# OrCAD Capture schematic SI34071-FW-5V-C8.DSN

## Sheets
1 1.ETH_TR: size B; title: Si34071-FW-5V-C8-Interface; rev: 3.1; note: SI34071-FW-5V-C8
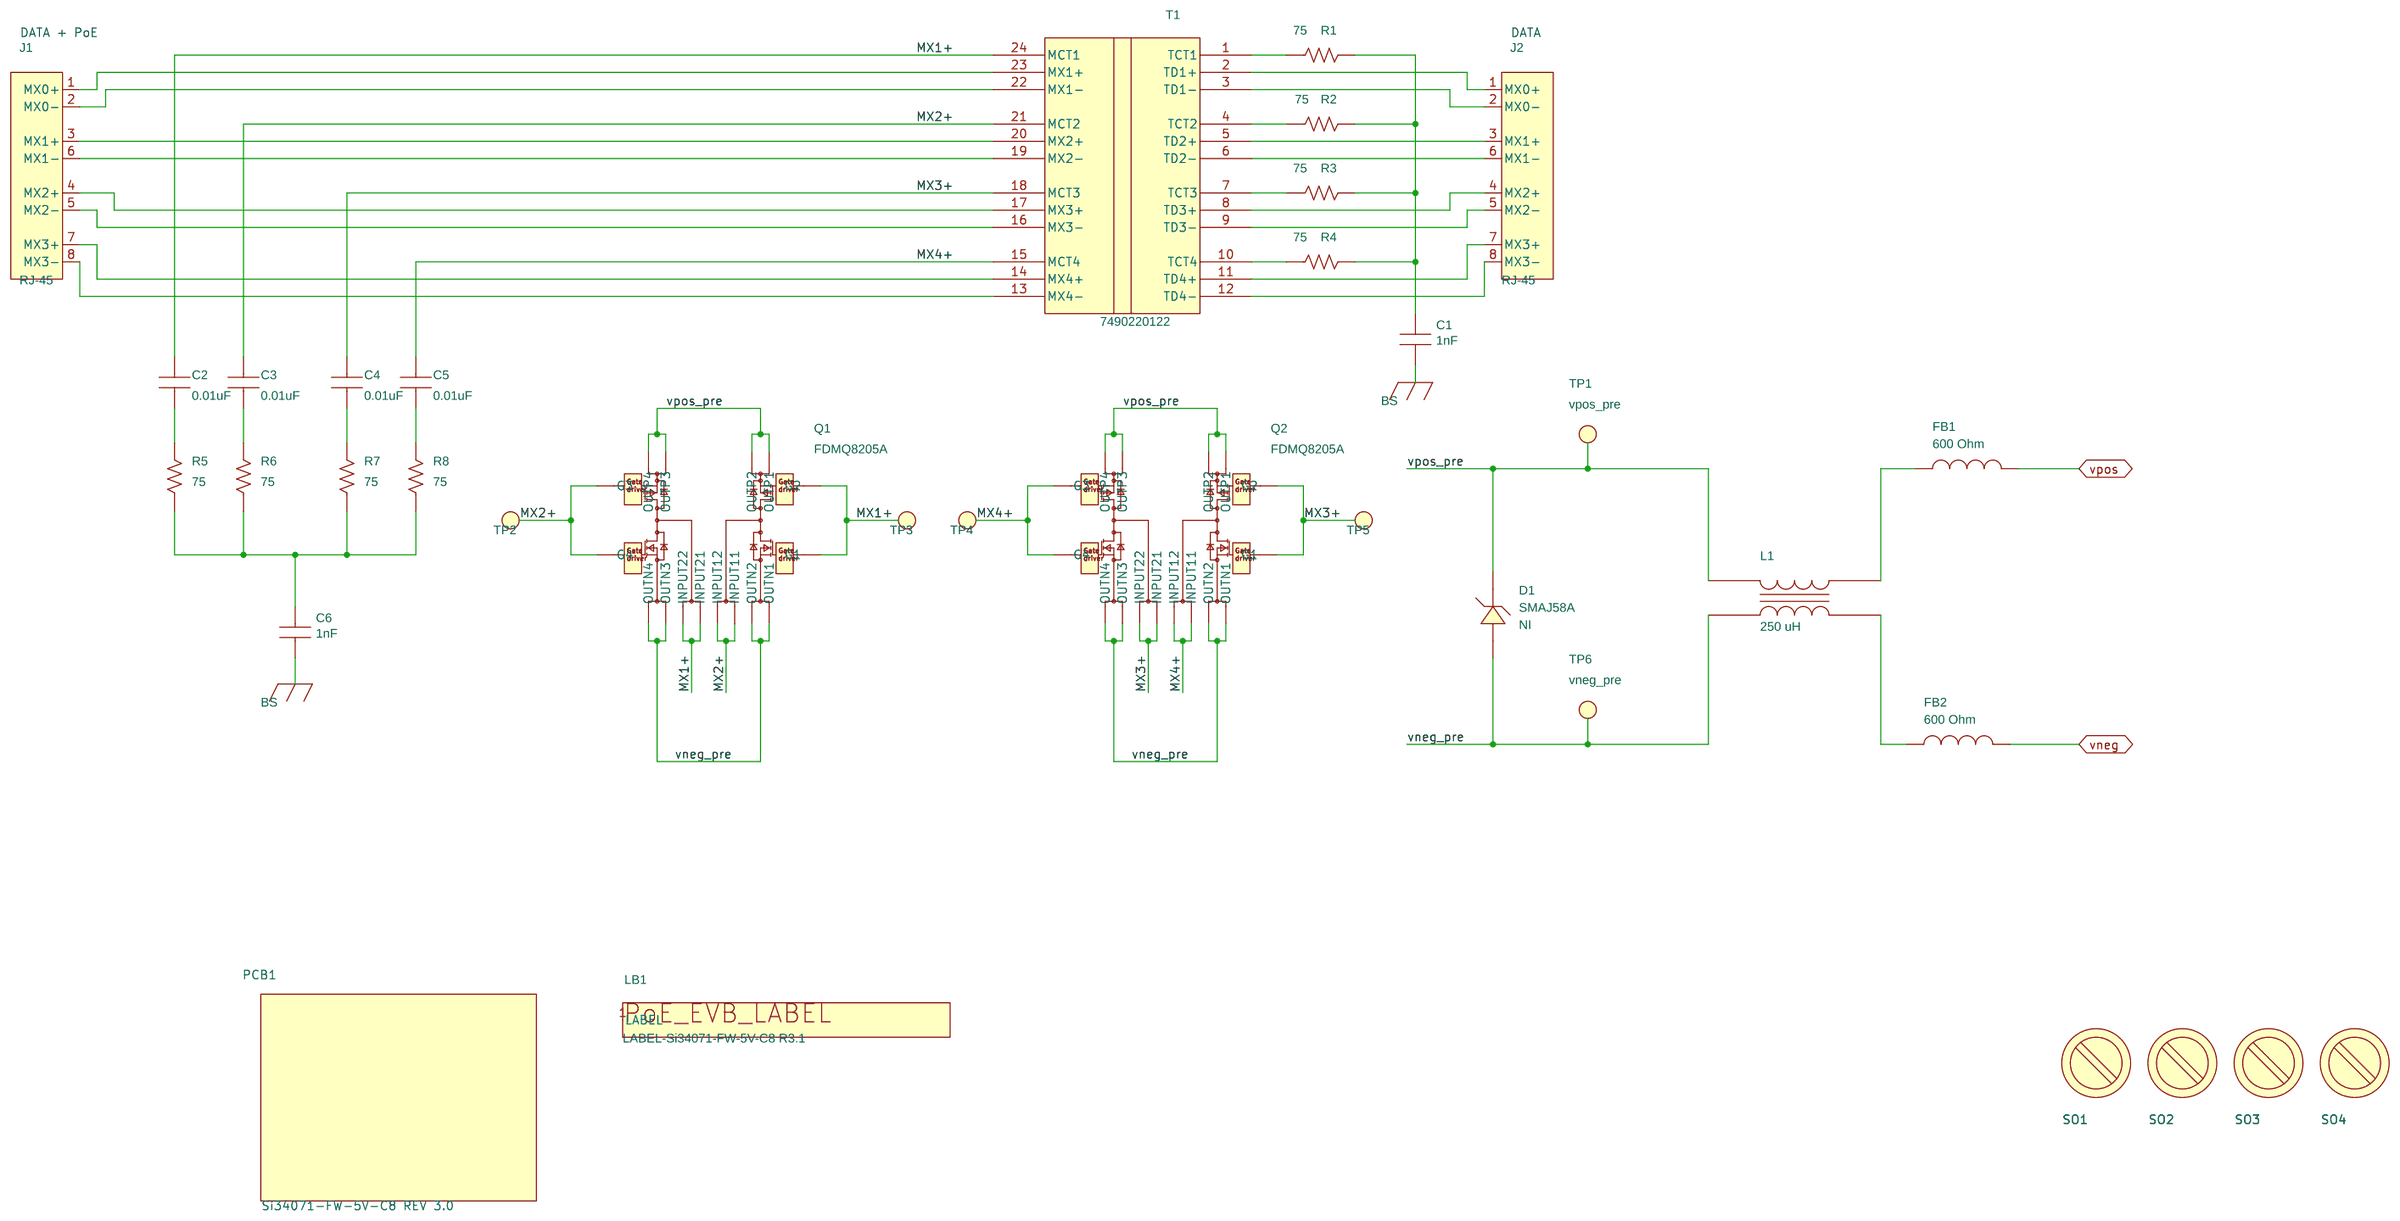
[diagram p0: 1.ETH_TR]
2 2.CLS_BOM: size B; title: Si34071-FW-5V-C8-Classification-BOM + MCU tx/rx
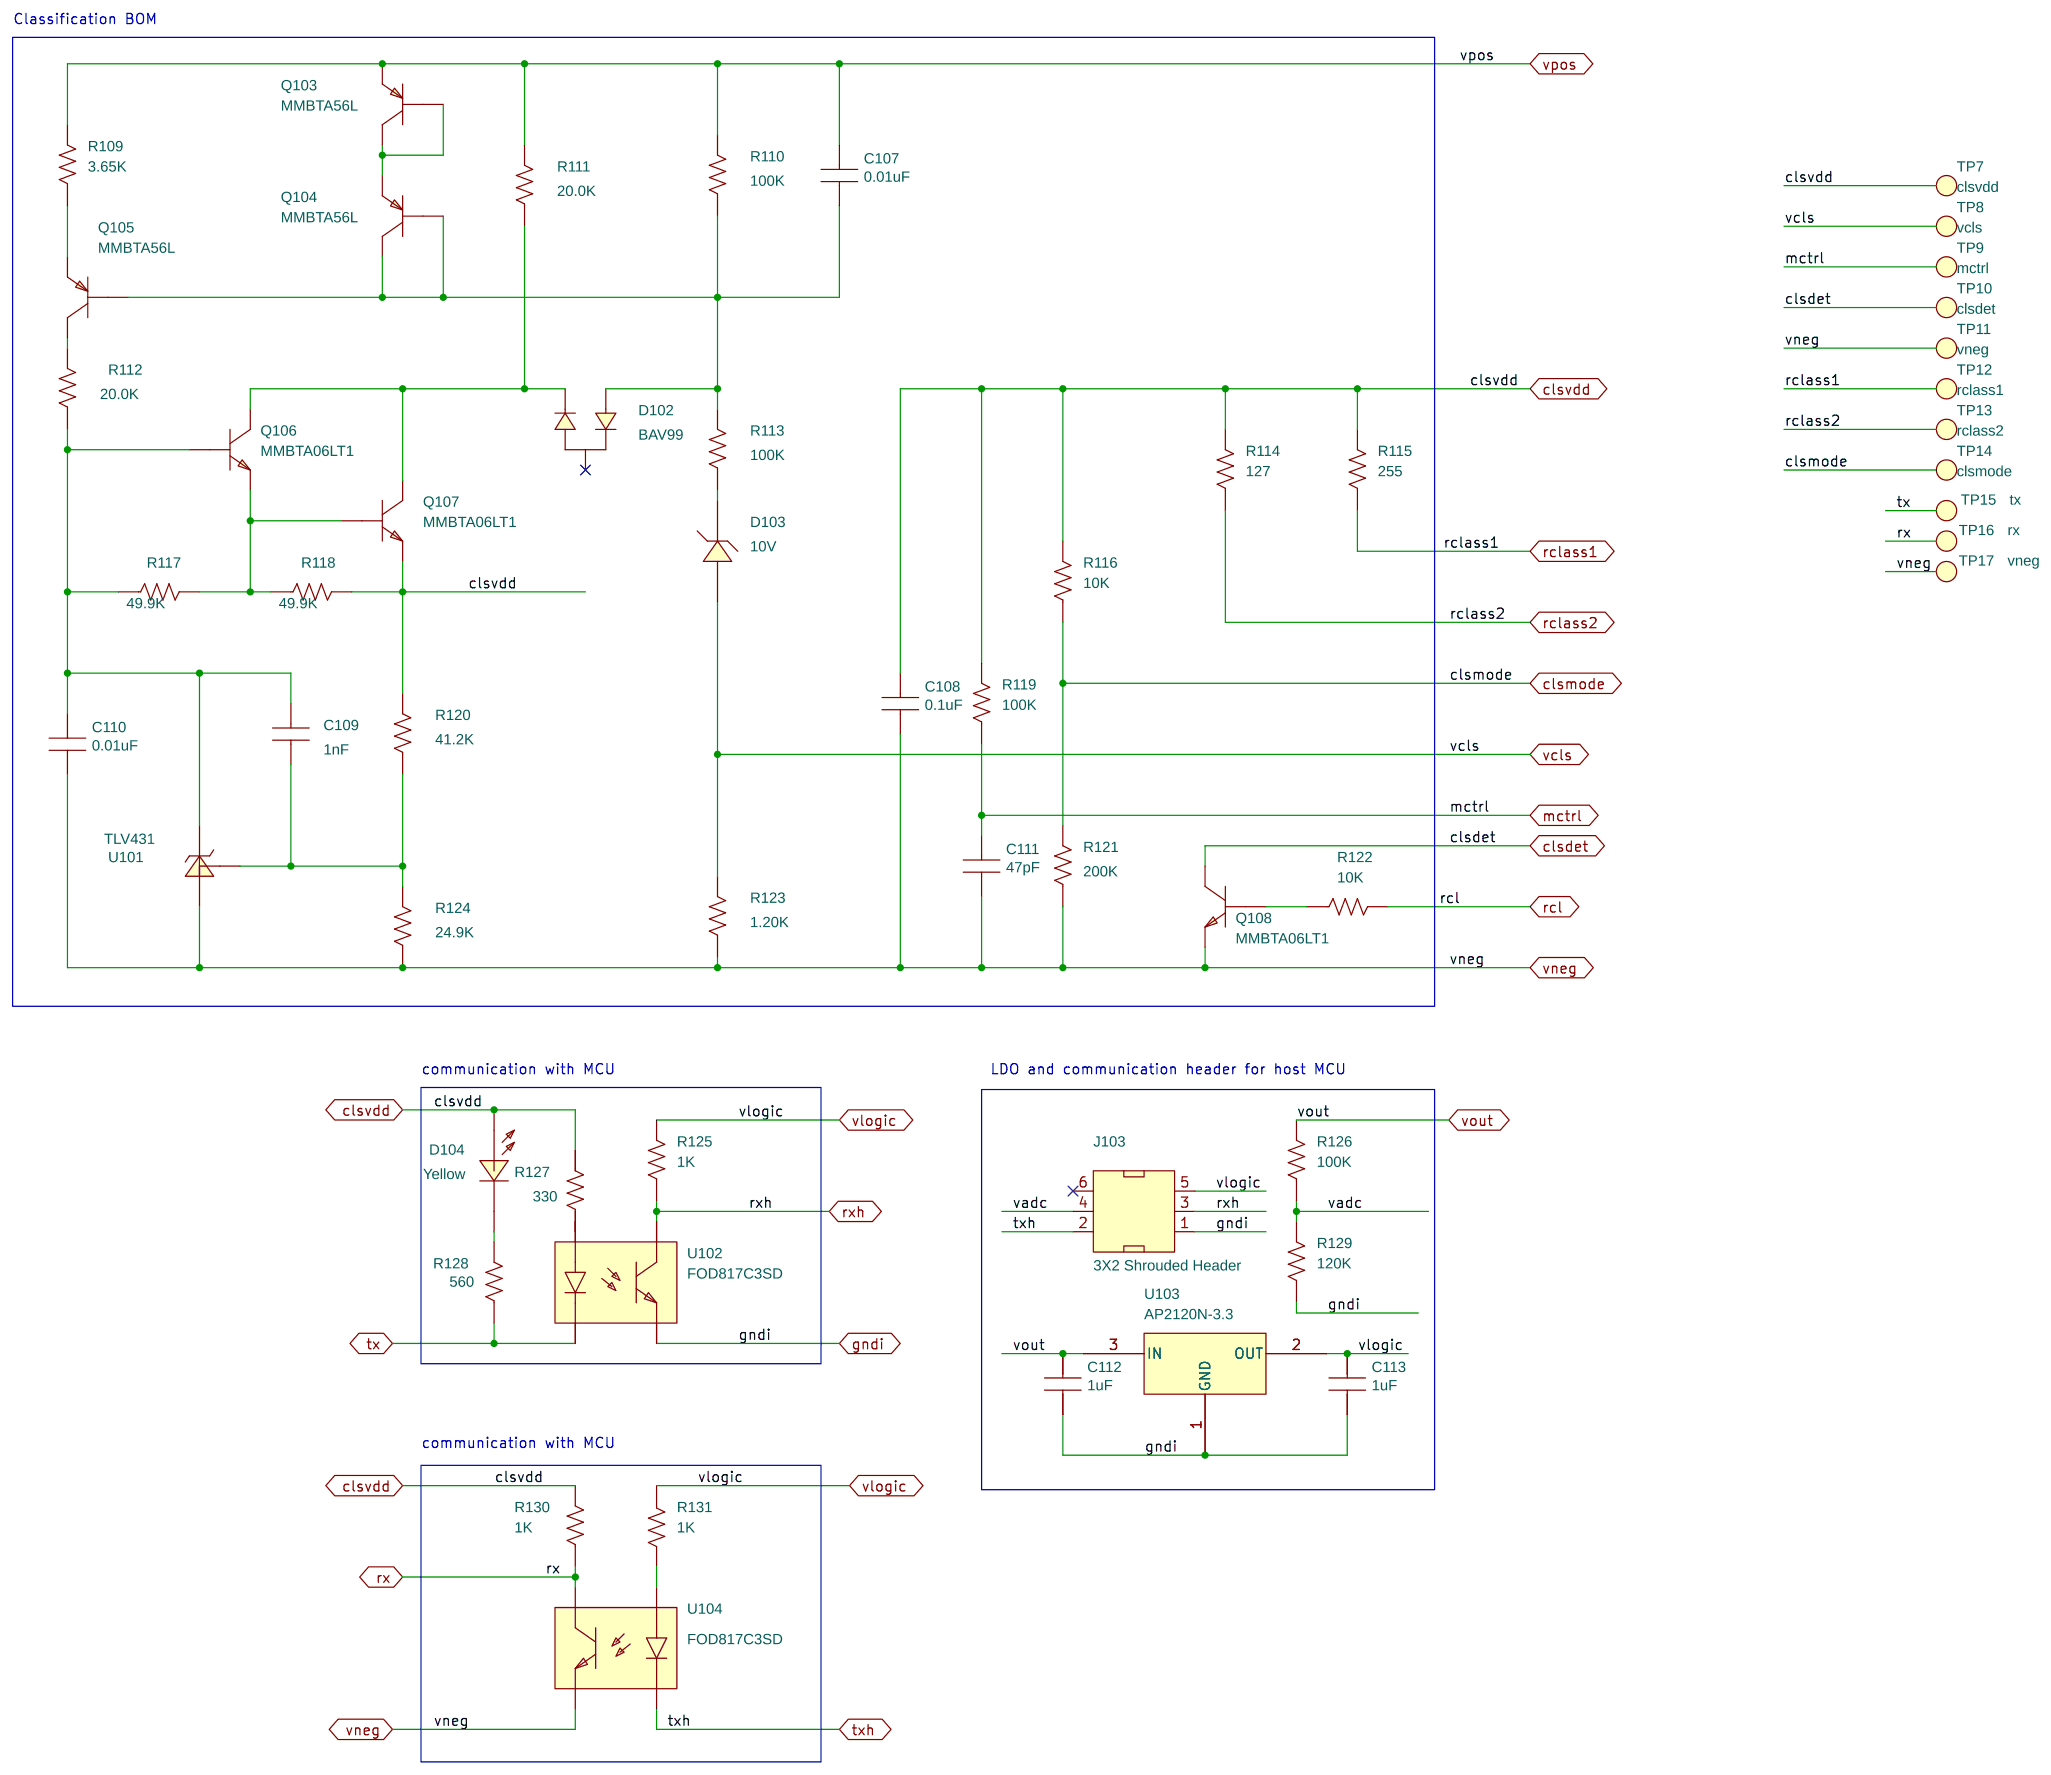
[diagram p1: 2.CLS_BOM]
3 3.DCDC: size B; title: Si34071-FW-5V-C8-Converter
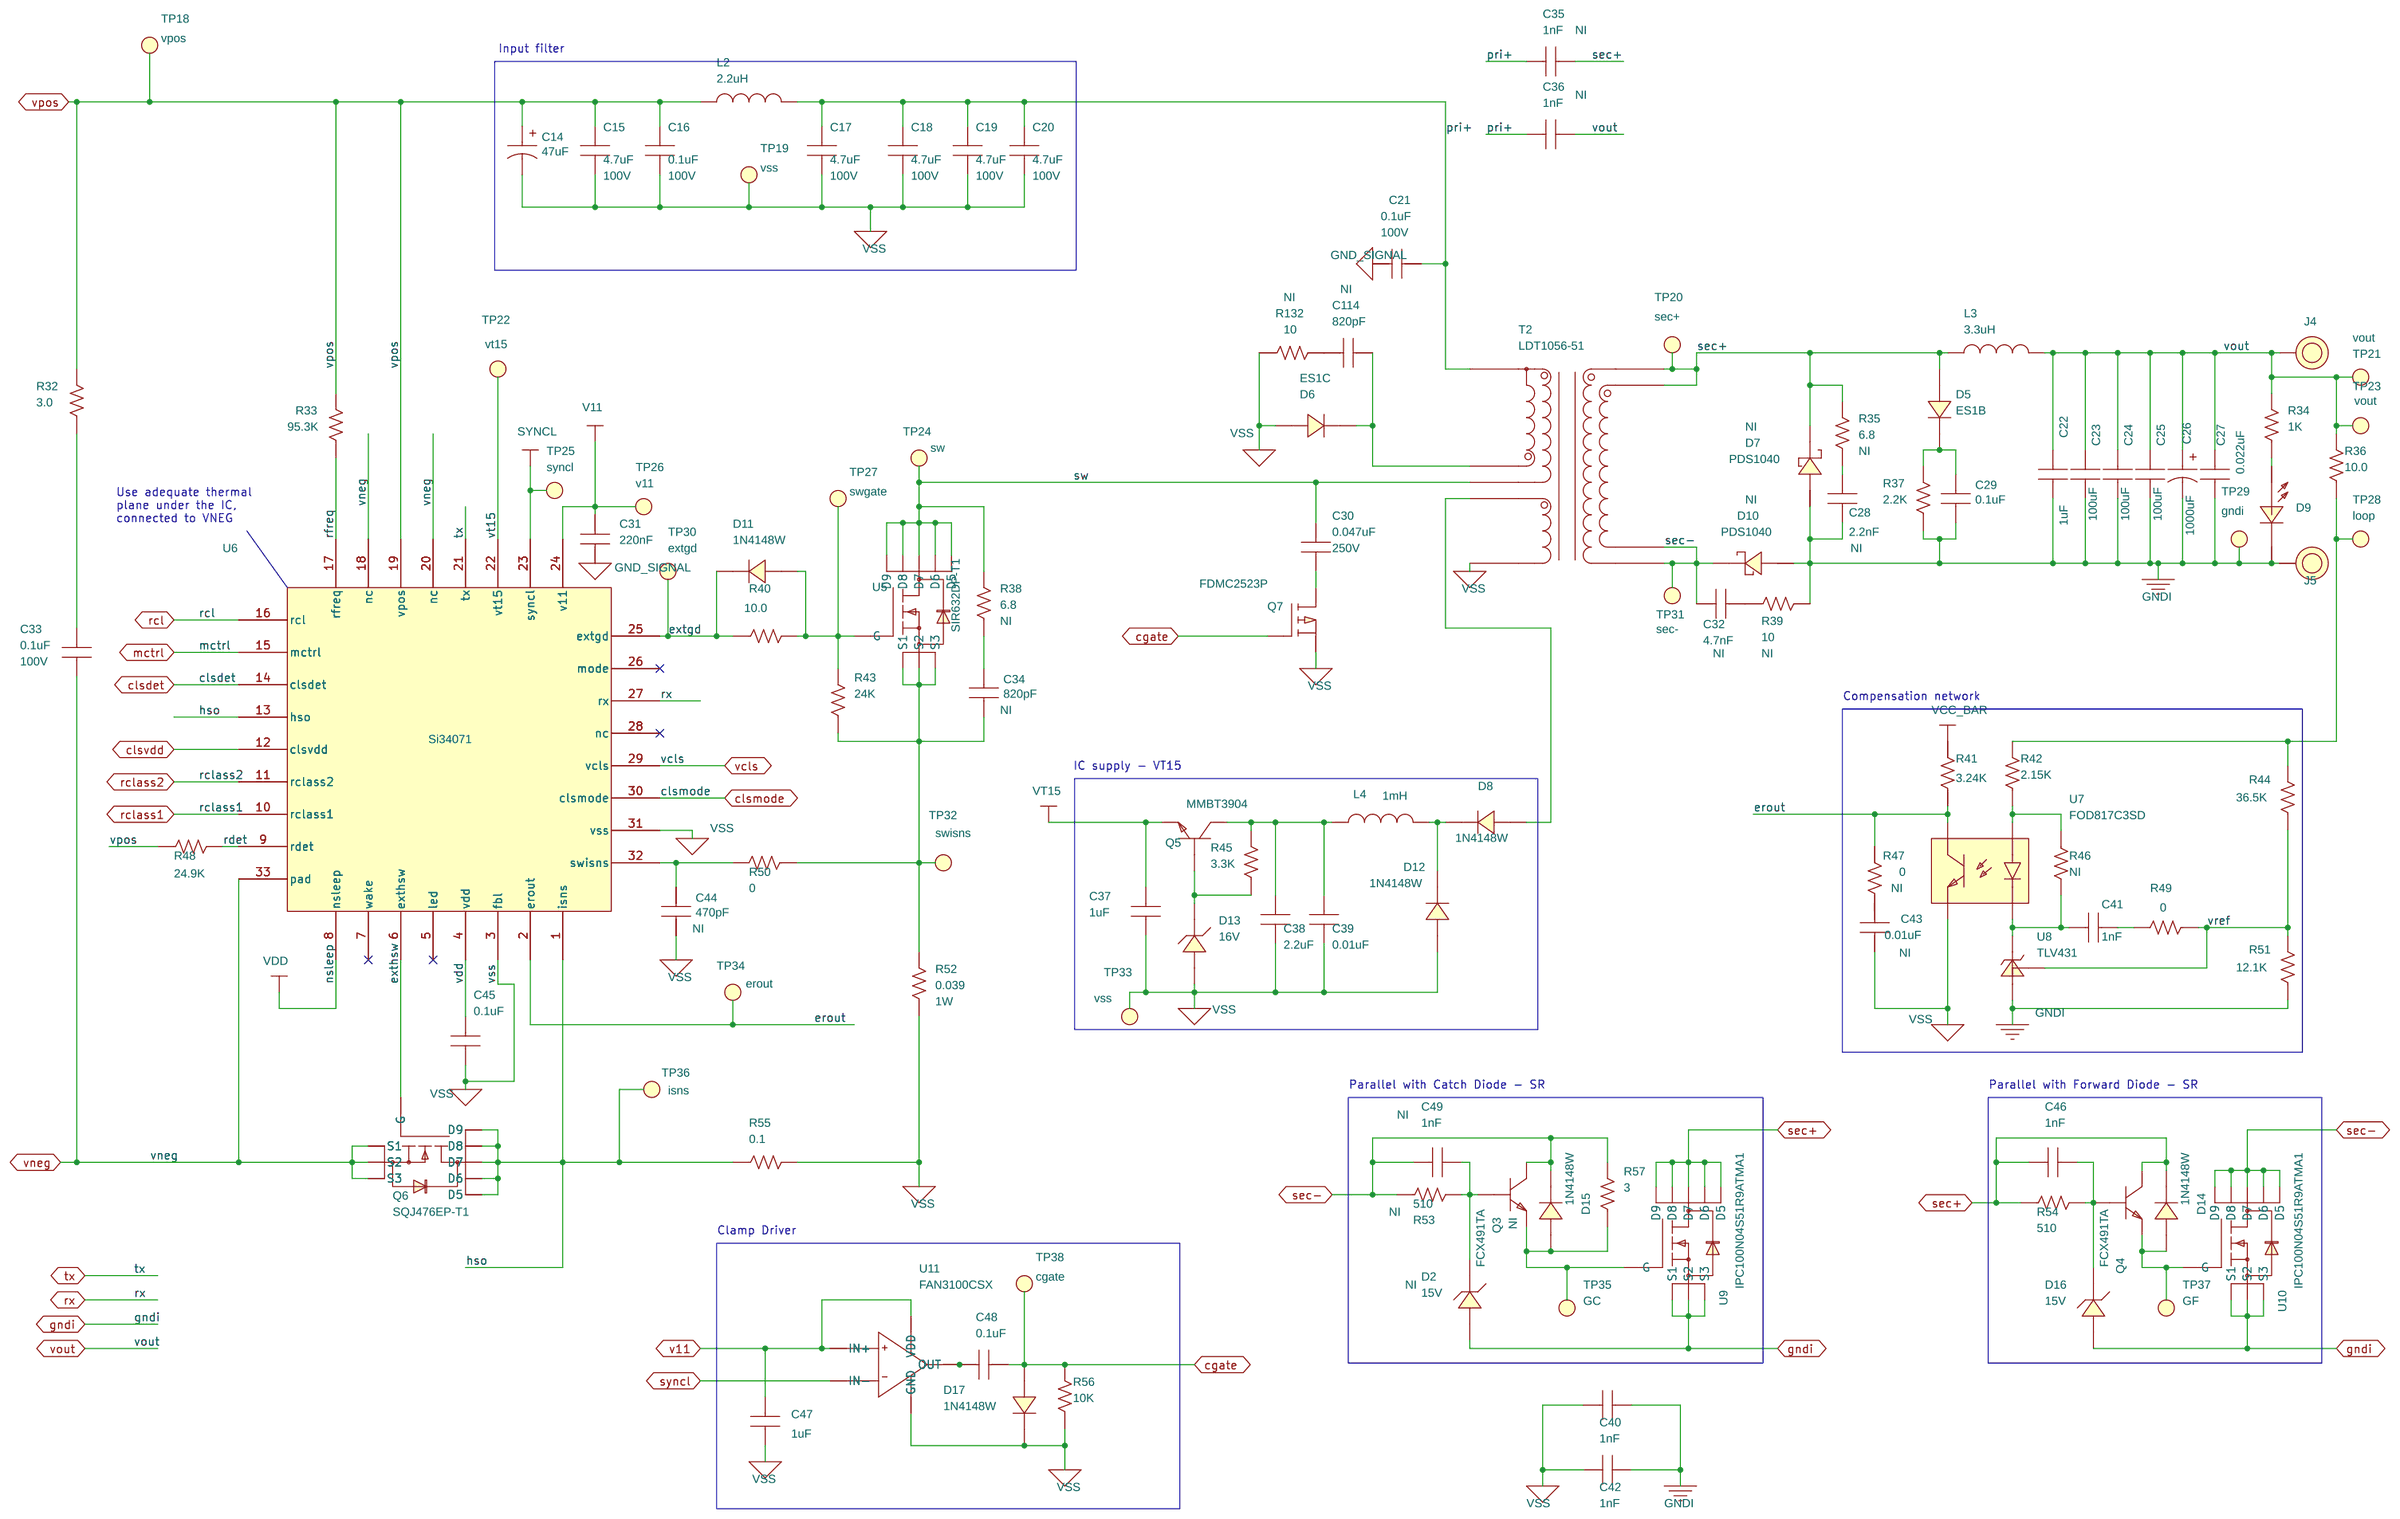
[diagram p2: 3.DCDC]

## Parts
sheet 1.ETH_TR
C1  1nF  [C1206]
C2  0.01uF  [C0603]
C3  0.01uF  [C0603]
C4  0.01uF  [C0603]
C5  0.01uF  [C0603]
C6  1nF  [C1206]
D1  SMAJ58A  [DO-214AC]
FB1  600 Ohm  [L1206]
FB2  600 Ohm  [L1206]
J1  RJ-45  [RJ45-95001]
J2  RJ-45  [RJ45-95001]
L1  250 uH  [IND-744272251]
LB1  LABEL-Si34071-FW-5V-C8 R3.1  [PTL-14-717]
MH1  4-40  [MH-125NP]
MH2  4-40  [MH-125NP]
MH3  4-40  [MH-125NP]
MH4  4-40  [MH-125NP]
PCB1  Si34071-FW-5V-C8 REV 3.0  [N/A]
Q1  FDMQ8205A  [DFN12N4.5X5.0P0.8EX4]
Q2  FDMQ8205A  [DFN12N4.5X5.0P0.8EX4]
R1  75  [R0603]
R2  75  [R0603]
R3  75  [R0603]
R4  75  [R0603]
R5  75  [R0603]
R6  75  [R0603]
R7  75  [R0603]
R8  75  [R0603]
SO1  STANDOFF
SO2  STANDOFF
SO3  STANDOFF
SO4  STANDOFF
T1  7490220122  [ETH-7490220121]
TP1  BLACK  [TESTPOINT]
TP2  BLACK  [TESTPOINT]
TP3  BLACK  [TESTPOINT]
TP4  BLACK  [TESTPOINT]
TP5  BLACK  [TESTPOINT]
TP6  BLACK  [TESTPOINT]
sheet 2.CLS_BOM
C107  0.01uF  [C0603]
C108  0.1uF  [C0603]
C109  1nF  [C0603]
C110  0.01uF  [C0603]
C111  47pF  [C0603]
C112  1uF  [C0603]
C113  1uF  [C0603]
D102  BAV99  [SOT23-AKC]
D103  10V  [SOD-123]
D104  Yellow  [LED-0603]
J103  3X2 Shrouded Header  [CONN2X3-4W]
Q103  MMBTA56L  [SOT23-BEC]
Q104  MMBTA56L  [SOT23-BEC]
Q105  MMBTA56L  [SOT23-BEC]
Q106  MMBTA06LT1  [SOT23-BEC]
Q107  MMBTA06LT1  [SOT23-BEC]
Q108  MMBTA06LT1  [SOT23-BEC]
R109  3.65K  [R0603]
R110  100K  [R0603]
R111  20.0K  [R0603]
R112  20.0K  [R0603]
R113  100K  [R0603]
R114  127  [R0603]
R115  255  [R0603]
R116  10K  [R0603]
R117  49.9K  [R0603]
R118  49.9K  [R0603]
R119  100K  [R0603]
R120  41.2K  [R0603]
R121  200K  [R0603]
R122  10K  [R0603]
R123  1.20K  [R0603]
R124  24.9K  [R0603]
R125  1K  [R0603]
R126  100K  [R0603]
R127  330  [R0603]
R128  560  [R0603]
R129  120K  [R0603]
R130  1K  [R0603]
R131  1K  [R0603]
TP7  BLACK  [TESTPOINT]
TP8  BLACK  [TESTPOINT]
TP9  BLACK  [TESTPOINT]
TP10  BLACK  [TESTPOINT]
TP11  BLACK  [TESTPOINT]
TP12  BLACK  [TESTPOINT]
TP13  BLACK  [TESTPOINT]
TP14  BLACK  [TESTPOINT]
TP15  BLACK  [TESTPOINT]
TP16  BLACK  [TESTPOINT]
TP17  BLACK  [TESTPOINT]
U101  TLV431  [TLV431-DBZ]
U102  FOD817C3SD  [SO4N10.16P2.54-AKEC]
U103  AP2120N-3.3  [SOT-23]
U104  FOD817C3SD  [SO4N10.16P2.54-AKEC]
sheet 3.DCDC
C14  47uF  [C3.5X8MM-RAD]
C15  4.7uF  [C1210]
C16  0.1uF  [C0603]
C17  4.7uF  [C1210]
C18  4.7uF  [C1210]
C19  4.7uF  [C1210]
C20  4.7uF  [C1210]
C21  0.1uF  [C0603]
C22  1uF  [C0603]
C23  100uF  [C1210]
C24  100uF  [C1210]
C25  100uF  [C1210]
C26  1000uF  [C3.5X8MM-RAD]
C27  0.022uF  [C0603]
C28  2.2nF  [C0603]
C29  0.1uF  [C0805]
C30  0.047uF  [C1206]
C31  220nF  [C0603]
C32  4.7nF  [C0603]
C33  0.1uF  [C0603]
C34  820pF  [C0805]
C35  1nF  [C1206]
C36  1nF  [C1206]
C37  1uF  [C0805]
C38  2.2uF  [C0603]
C39  0.01uF  [C0603]
C40  1nF  [C1206]
C41  1nF  [C0603]
C42  1nF  [C1206]
C43  0.01uF  [C0603]
C44  470pF  [C0603]
C45  0.1uF  [C0603]
C46  1nF  [C0603]
C47  1uF  [C0805]
C48  0.1uF  [C0805]
C49  1nF  [C0603]
C114  820pF  [C0805]
D2  15V  [SOD123]
D5  ES1B  [DO-214AC]
D6  ES1C  [DO-214AC]
D7  PDS1040  [POWERDI-5]
D8  1N4148W  [SOD-123]
D9  GREEN  [LED-0603]
D10  PDS1040  [POWERDI-5]
D11  1N4148W  [SOD-123]
D12  1N4148W  [SOD-123]
D13  16V  [SOD-123]
D14  1N4148W  [SOD-123]
D15  1N4148W  [SOD-123]
D16  15V  [SOD123]
D17  1N4148W  [SOD-123]
J4  BND_POST  [BANANA-JACK]
J5  BND_POST  [BANANA-JACK]
L2  2.2uH  [IND-8400]
L3  3.3uH  [IND-XAL1010]
L4  1mH  [IND-2020-WURTH]
Q3  FCX491TA  [SOT89-BCE]
Q4  FCX491TA  [SOT89-BCE]
Q5  MMBT3904  [SOT23-BEC]
Q6  SQJ476EP-T1  [POWER56]
Q7  FDMC2523P  [POWER33]
R32  3.0  [R0603]
R33  95.3K  [R0603]
R34  1K  [R0603]
R35  6.8  [R1206]
R36  10.0  [R0603]
R37  2.2K  [R1206]
R38  6.8  [R1206]
R39  10  [R1206]
R40  10.0  [R0603]
R41  3.24K  [R0603]
R42  2.15K  [R0603]
R43  24K  [R0603]
R44  36.5K  [R0603]
R45  3.3K  [R0805]
R46  1K  [R0603]
R47  0  [R0603]
R48  24.9K  [R0603]
R49  0  [R0603]
R50  0  [R0603]
R51  12.1K  [R0603]
R52  0.039  [R1206]
R53  510  [R0603]
R54  510  [R0603]
R55  0.1  [R1206]
R56  10K  [R0805]
R57  3  [R0805]
R132  10  [R1206]
T2  LDT1056-51  [XFMR-LDT1056-50]
TP18  BLACK  [TESTPOINT]
TP19  BLACK  [TESTPOINT]
TP20  BLACK  [TESTPOINT]
TP21  BLACK  [TESTPOINT]
TP22  BLACK  [TESTPOINT]
TP23  BLACK  [TESTPOINT]
TP24  BLACK  [TESTPOINT]
TP25  BLACK  [TESTPOINT]
TP26  BLACK  [TESTPOINT]
TP27  BLACK  [TESTPOINT]
TP28  BLACK  [TESTPOINT]
TP29  BLACK  [TESTPOINT]
TP30  BLACK  [TESTPOINT]
TP31  BLACK  [TESTPOINT]
TP32  BLACK  [TESTPOINT]
TP33  BLACK  [TESTPOINT]
TP34  BLACK  [TESTPOINT]
TP35  BLACK  [TESTPOINT]
TP36  BLACK  [TESTPOINT]
TP37  BLACK  [TESTPOINT]
TP38  BLACK  [TESTPOINT]
U5  SIR632DP-T1  [POWER56]
U6  Si34071  [QFN32N5X5P0.5E3.5]
U7  FOD817C3SD  [SO4N10.16P2.54-AKEC]
U8  TLV431  [TLV431-DBZ]
U9  IPC100N04S51R9ATMA1  [POWER56]
U10  IPC100N04S51R9ATMA1  [POWER56]
U11  FAN3100CSX  [SOT23-5N]

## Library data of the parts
C1 C6 C40 C42 = CAP_NP: CAP, 1nF, 2000V, ±5%, X7R, 1206; Manufacturer: Kemet; ManufacturerPN: C1206C102JGRACTU; SiLabsPN: C1206C102JGRACTU; Tolerance: ±5%; Type: X7R; Voltage: 2000V; Datasheet: KEM_C1010_X7R_HV_SMD-1102742.pdf
C2-C5 C107 C110 = CAP_NP: CAP, 0.01uF, 100V, ±10%, X7R, 0603; Manufacturer: Venkel; ManufacturerPN: C0603X7R101-103K; SiLabsPN: C0603X7R101-103K; Tolerance: ±10%; Type: X7R; Voltage: 100V; Datasheet: PID_C.pdf
D1 = DIODE_ZENER: DIO, TVS, UNIDIR, 58V, 400W; Installed Component: NI; Manufacturer: Littelfuse; Rating: 400W; Type: GP; Voltage: 58V; Datasheet: smaj.pdf
FB1 FB2 = Ferrite_Bead: FERRITE BEAD, 600 Ohm @100MHZ, 1206; Manufacturer: Wurth; ManufacturerPN: 742792118; Rating: 2500mA; SiLabsPN: 742792118; Type: SMT; Datasheet: 742792118.pdf
J1 = RJ45_1PORT: CONN, RJ-45, 1 Port, Tab Down, 0.050" Pitch, PTH; Manufacturer: MOLEX; ManufacturerPN: 95001-2881; SiLabsPN: 95001-2881; Silk: PoE+Data; Type: Receptacle; Datasheet: 950012881_sd.pdf
J2 = RJ45_1PORT: CONN, RJ-45, 1 Port, Tab Down, 0.050" Pitch, PTH; Manufacturer: MOLEX; ManufacturerPN: 95001-2881; SiLabsPN: 95001-2881; Silk: Data; Type: Receptacle; Datasheet: 950012881_sd.pdf
L1 = CHOKE_CM_4P_744272251: CM Choke, 2x250uH, 2A, 970 ohm, SMT; Manufacturer: Würth; ManufacturerPN: 744272251; Rating: 0.035 ohm; SiLabsPN: 744272251; Type: Ethernet; Voltage: 80VDC; Datasheet: 744272251.pdf
LB1 = PoE_EVB_Label: LABEL, PDB, POLYIMIDE, WHITE, 1.00 in. X 0.187 in., FONT 2; Manufacturer: Skyworks; Type: POLYIMIDE, WHITE; Datasheet: Brady TLS2200 Label PTL-14-717.pdf
MH1-MH4 = SCREW-Small: HDW, SCREW, 4-40 x 1/4 in. Pan Head, Slotted, Nylon; Manufacturer: Richco Plastic Co; ManufacturerPN: NSS-4-4-01; SiLabsPN: NSS-4-4-01; Type: SCREW; Datasheet: RichcoPlasticCo_Screws.pdf
PCB1 = PCB: PCB, BARE BOARD, Si34071-FW-5V-C8 REV 3.0; Manufacturer: Skyworks; Type: BARE PCB
Q1 Q2 = FDMQ8205A: IC, MOSFET BRIDGE RECTIFIER, N-CHNL, P-CHNL, 100V, 3.4A, -2.6A, WDFN12; Manufacturer: OnSemi; Rating: 3.4A, -2.6A; Type: Bridge Rectifier; Voltage: 100V; Datasheet: FDMQ8205A-D.pdf
R1-R8 = RES: RES, 75 Ohm, 1/16W, ±0.5%, ThinFilm, 0603; Manufacturer: Susumu; ManufacturerPN: RR0816Q-750-D; Rating: 1/16W; SiLabsPN: RR0816Q-750-D; Tolerance: ±0.5%; Type: ThinFilm; Datasheet: products_12.pdf
SO1-SO4 = STANDOFF: HDW, STANDOFF, 4-40 X 1/2" , Nylon; Manufacturer: SPC Technology; ManufacturerPN: 2397; SiLabsPN: 2397; Datasheet: SPC_Technology_spacers.pdf
T1 = ETH-7490220121: Module, PoE+/PoE++ Magnetics, PULSE XFMR 1CT:1CT TX 1CT:1CT RX, SMD; Manufacturer: Wurth; Rating: 350uH; Type: Ethernet; Datasheet: 7490220122.pdf
TP1 = TEST_POINT: TESTPOINT, BLACK, PTH; Manufacturer: Kobiconn; ManufacturerPN: 151-203-RC; SiLabsPN: 151-203; Silk: vpos_pre; Type: Loop; Datasheet: KC-300780.pdf
TP2-TP5 = TEST_POINT: TESTPOINT, BLACK, PTH; Manufacturer: Kobiconn; ManufacturerPN: 151-203-RC; SiLabsPN: 151-203; Type: Loop; Datasheet: KC-300780.pdf
TP6 = TEST_POINT: TESTPOINT, BLACK, PTH; Manufacturer: Kobiconn; ManufacturerPN: 151-203-RC; SiLabsPN: 151-203; Silk: vneg_pre; Type: Loop; Datasheet: KC-300780.pdf
C108 = CAP_NP: CAP, 0.1uF, 25V, ±10%, X7R, 0603; Manufacturer: Venkel; ManufacturerPN: C0603X7R250-104K; SiLabsPN: C0603X7R250-104K; Tolerance: ±10%; Type: X7R; Voltage: 25V; Datasheet: PID_C.pdf
C109 = CAP_NP: CAP, 1nF, 100V, ±10%, X7R, 0603; Manufacturer: Venkel; ManufacturerPN: C0603X7R101-102K; SiLabsPN: C0603X7R101-102K; Tolerance: ±10%; Type: X7R; Voltage: 100V; Datasheet: PID_C.pdf
C111 = CAP_NP: CAP, 47pF, 100V, ±10%, X7R, 0603; Manufacturer: Venkel; ManufacturerPN: C0603X7R101-470K; SiLabsPN: C0603X7R101-470K; Tolerance: ±10%; Type: X7R; Voltage: 100V; Datasheet: PID_C.pdf
C112 C113 = CAP_NP: CAP, 1uF, 6.3V, ±10%, X5R, 0603; Manufacturer: Venkel; ManufacturerPN: C0603X5R6R3-105K; SiLabsPN: C0603X5R6R3-105K; Tolerance: ±10%; Type: X5R; Voltage: 6.3V; Datasheet: PID_C.pdf
D102 = DIODE_DUAL_SERIES: DIO, DUAL, SWITCH, 100V, 300mA, SOT23; Manufacturer: Diodes Inc.; ManufacturerPN: BAV99-7-F; Rating: 300mA; SiLabsPN: BAV99-7-F; Type: Dual, Switch; Voltage: 100V; Datasheet: DiodesIncBAV99.pdf
D103 = DIODE_ZENER: DIO, ZENER, 10V, 500mW, SOD123; Manufacturer: On Semi; ManufacturerPN: MMSZ4697T1G; Rating: 500mW; SiLabsPN: MMSZ4697T1G; Tolerance: 5%; Type: Zener; Datasheet: MMSZ4678T1-D.pdf
D104 = LED: LED, Yellow, 2mA, 1.8V, 7.5mcd, 0603; Manufacturer: Vishay; ManufacturerPN: TLMY1000-GS08; Rating: 15mA; SiLabsPN: TLMY1000-GS08; Datasheet: tlmo1000.pdf
J103 = CONN_3x2: CONN, HEADER, SHROUDED, 2X3, 0.1in, STR, Au; Manufacturer: 3M; ManufacturerPN: 30306-6002HB; SiLabsPN: 30306-6002HB; Type: Shrouded; Datasheet: TS0818.pdf
Q103-Q105 = PNP_3PIN: TRANSISTOR, PNP, -80V, 500mA, DRIVER, SOT23; Manufacturer: On Semi; Part_Type: XTR/BJT; Rating: 500mA; Type: PNP; Voltage: -80V; Datasheet: MMBTA55LT1-D.pdf
Q106-Q108 = NPN_3PIN: TRANSISTOR, NPN, 80V, 500mA, DRIVER, SOT23; Manufacturer: On Semi; Rating: 500mA; Type: NPN; Voltage: 80V; Datasheet: MMBTA05LT1-D.pdf
R109 = RES: RES, 3.65K, 1/16W, ±1%, ThickFilm, 0603; Manufacturer: Venkel; ManufacturerPN: CR0603-16W-3651FT; Rating: 1/16W; SiLabsPN: CR0603-16W-3651F; Tolerance: ±1%; Type: ThickFilm; Datasheet: PID_CR.pdf
R110 R113 R119 R126 = RES: RES, 100K, 1/10W, ±1%, ThickFilm, 0603; Manufacturer: Venkel; ManufacturerPN: CR0603-10W-1003F; Rating: 1/10W; SiLabsPN: CR0603-10W-1003F; Tolerance: ±1%; Type: ThickFilm; Datasheet: PID_CR.pdf
R111 R112 = RES: RES, 20.0K, 1/16W, ±1%, ThickFilm, 0603; Manufacturer: Venkel; ManufacturerPN: CR0603-16W-2002F; Rating: 1/16W; SiLabsPN: CR0603-16W-2002F; Tolerance: ±1%; Type: ThickFilm; Datasheet: PID_CR.pdf
R114 = RES: RES, 127 Ohm, 1/10W, ±1%, ThickFilm, 0603; Manufacturer: Venkel; ManufacturerPN: CR0603-10W-1270F; Rating: 1/10W; SiLabsPN: CR0603-10W-1270F; Tolerance: ±1%; Type: ThickFilm; Datasheet: PID_CR.pdf
R115 = RES: RES, 255 Ohm, 1/10W, ±1%, ThickFilm, 0603; Manufacturer: Venkel; ManufacturerPN: CR0603-10W-2550F; Rating: 1/10W; SiLabsPN: CR0603-10W-2550F; Tolerance: ±1%; Type: ThickFilm; Datasheet: PID_CR.pdf
R116 R122 = RES: RES, 10K, 1/16W, ±1%, ThickFilm, 0603; Manufacturer: Venkel; ManufacturerPN: CR0603-16W-1002F; Rating: 1/16W; SiLabsPN: CR0603-16W-1002F; Tolerance: ±1%; Type: ThickFilm; Datasheet: PID_CR.pdf
R117 R118 = RES: RES, 49.9K, 1/10W, ±1%, ThickFilm, 0603; Manufacturer: Venkel; ManufacturerPN: CR0603-10W-4992F; Rating: 1/10W; SiLabsPN: CR0603-10W-4992F; Tolerance: ±1%; Type: ThickFilm; Datasheet: PID_CR.pdf
R120 = RES: RES, 41.2K, 1/10W, ±1%, ThickFilm, 0603; Manufacturer: Venkel; ManufacturerPN: CR0603-10W-4122F; Rating: 1/10W; SiLabsPN: CR0603-10W-4122F; Tolerance: ±1%; Type: ThickFilm; Datasheet: PID_CR.pdf
R121 = RES: RES, 200K, 1/10W, ±5%, ThickFilm, 0603; Manufacturer: Bourns; ManufacturerPN: CR0603-JW-204ELF; Rating: 1/10W; SiLabsPN: CR0603-10W-204J; Tolerance: ±5%; Type: ThickFilm; Datasheet: CHPREZTR.pdf
R123 = RES: RES, 1.20K, 1/10W, ±1%, ThickFilm, 0603; Manufacturer: Venkel; ManufacturerPN: CR0603-10W-1201F; Rating: 1/10W; SiLabsPN: CR0603-10W-1201F; Tolerance: ±1%; Type: ThickFilm; Datasheet: PID_CR.pdf
R48 R124 = RES: RES, 24.9K, 1/10W, ±1%, ThickFilm, 0603; Manufacturer: Venkel; ManufacturerPN: CR0603-10W-2492F; Rating: 1/10W; SiLabsPN: CR0603-10W-2492F; Tolerance: ±1%; Type: ThickFilm; Datasheet: PID_CR.pdf
R34 R125 R130 R131 = RES: RES, 1K, 1/10W, ±1%, ThickFilm, 0603; Manufacturer: Venkel; ManufacturerPN: CR0603-10W-1001F; Rating: 1/10W; SiLabsPN: CR0603-10W-1001F; Tolerance: ±1%; Type: ThickFilm; Datasheet: PID_CR.pdf
R127 = RES: RES, 330 Ohm, 1/16W, ±1%, ThickFilm, 0603; Manufacturer: Venkel; ManufacturerPN: CR0603-16W-3300F; Rating: 1/16W; SiLabsPN: CR0603-16W-3300F; Tolerance: ±1%; Type: ThickFilm; Datasheet: PID_CR.pdf
R128 = RES: RES, 560 Ohm, 1/10W, ±1%, ThickFilm, 0603; Manufacturer: Venkel; ManufacturerPN: CR0603-10W-5600F; Rating: 1/10W; SiLabsPN: CR0603-10W-5600F; Tolerance: ±1%; Type: ThickFilm; Datasheet: PID_CR.pdf
R129 = RES: RES, 120K, 1/10W, ±1%, ThickFilm, 0603; Manufacturer: Venkel; ManufacturerPN: CR0603-10W-1203F; Rating: 1/10W; SiLabsPN: CR0603-10W-1203F; Tolerance: ±1%; Type: ThickFilm; Datasheet: PID_CR.pdf
TP7 = TEST_POINT: TESTPOINT, BLACK, PTH; Manufacturer: Kobiconn; ManufacturerPN: 151-203-RC; SiLabsPN: 151-203; Silk: clsvdd; Type: Loop; Datasheet: KC-300780.pdf
TP8 = TEST_POINT: TESTPOINT, BLACK, PTH; Manufacturer: Kobiconn; ManufacturerPN: 151-203-RC; SiLabsPN: 151-203; Silk: vcls; Type: Loop; Datasheet: KC-300780.pdf
TP9 = TEST_POINT: TESTPOINT, BLACK, PTH; Manufacturer: Kobiconn; ManufacturerPN: 151-203-RC; SiLabsPN: 151-203; Silk: mctrl; Type: Loop; Datasheet: KC-300780.pdf
TP10 = TEST_POINT: TESTPOINT, BLACK, PTH; Manufacturer: Kobiconn; ManufacturerPN: 151-203-RC; SiLabsPN: 151-203; Silk: clsdet; Type: Loop; Datasheet: KC-300780.pdf
TP11 TP17 = TEST_POINT: TESTPOINT, BLACK, PTH; Manufacturer: Kobiconn; ManufacturerPN: 151-203-RC; SiLabsPN: 151-203; Silk: vneg; Type: Loop; Datasheet: KC-300780.pdf
TP12 = TEST_POINT: TESTPOINT, BLACK, PTH; Manufacturer: Kobiconn; ManufacturerPN: 151-203-RC; SiLabsPN: 151-203; Silk: rclass1; Type: Loop; Datasheet: KC-300780.pdf
TP13 = TEST_POINT: TESTPOINT, BLACK, PTH; Manufacturer: Kobiconn; ManufacturerPN: 151-203-RC; SiLabsPN: 151-203; Silk: rclass2; Type: Loop; Datasheet: KC-300780.pdf
TP14 = TEST_POINT: TESTPOINT, BLACK, PTH; Manufacturer: Kobiconn; ManufacturerPN: 151-203-RC; SiLabsPN: 151-203; Silk: clsmode; Type: Loop; Datasheet: KC-300780.pdf
TP15 = TEST_POINT: TESTPOINT, BLACK, PTH; Manufacturer: Kobiconn; ManufacturerPN: 151-203-RC; SiLabsPN: 151-203; Silk: tx; Type: Loop; Datasheet: KC-300780.pdf
TP16 = TEST_POINT: TESTPOINT, BLACK, PTH; Manufacturer: Kobiconn; ManufacturerPN: 151-203-RC; SiLabsPN: 151-203; Silk: rx; Type: Loop; Datasheet: KC-300780.pdf
U8 U101 = SHUNT_REG: IC, ADJ PREC SHUNT REG LV SOT-23 Voltage-Output 1.24 ~ 6V; Manufacturer: TI; ManufacturerPN: TLV431BCDBZR; SiLabsPN: TLV431BCDBZR; Type: SHUNT; Datasheet: tlv431a.pdf
U7 U102 U104 = OPTOCOUPLER: PHOTOCOUPLER, 5000Vrms Isolation, 4-PIN SMD; Manufacturer: Vishay; Datasheet: FOD814-D.PDF
U103 = REG_3-TERM_3P-GOI: IC, VOLTAGE REGULATOR, LDO, HIGH SPEED, EXTREMELY LOW NOISE, SOT23; Manufacturer: Diodes Inc.; Rating: 100mA; Type: LDO; Voltage: 3.3V; Datasheet: AP2120.pdf
C14 = CAP_POL_ALT: CAP, 47uF, 100V, ±20%, AL, RAD; Manufacturer: Panasonic; ManufacturerPN: ECA2AM470; SiLabsPN: ECA2AM470; Tolerance: ±20%; Type: Alum_Elec; Voltage: 100V; Datasheet: ABA0000CE12.pdf
C15 C17-C20 = CAP_NP: CAP, 4.7uF, 100V, ±10%, X7R, 1210; Manufacturer: Venkel; ManufacturerPN: C1210X7R101-475KNE; SiLabsPN: C1210X7R101-475K; Tolerance: ±10%; Type: X7R; Voltage: 100V; Datasheet: PID_C.pdf
C16 C21 C33 = CAP_NP: CAP, 0.1uF, 100V, ±10%, X7R, 0603; Manufacturer: Venkel; ManufacturerPN: C0603X7R101-104K; SiLabsPN: C0603X7R101-104K; Tolerance: ±10%; Type: X7R; Voltage: 100V; Datasheet: PID_C.pdf
C22 = CAP_NP: CAP, 1uF, 16V, ±10%, X5R, 0603; Manufacturer: Venkel; ManufacturerPN: C0603X5R160-105K; SiLabsPN: C0603X5R160-105K; Tolerance: ±10%; Type: X5R; Voltage: 16V; Datasheet: PID_C.pdf
C23-C25 = CAP_NP: CAP, 100uF, 6.3V, ±10%, X5R, 1210; Manufacturer: Venkel; ManufacturerPN: C1210X5R6R3-107K; SiLabsPN: C1210X5R6R3-107K; Tolerance: ±10%; Type: X5R; Voltage: 6.3V; Datasheet: PID_C.pdf
C26 = CAP_POL_ALT: CAP, 1000uF, 6.3V, ±20%, AL, 8X11.5MM; Manufacturer: Panasonic; ManufacturerPN: ECA0JM102; SiLabsPN: ECA0JM102; Tolerance: ±20%; Type: Alum_Elec; Voltage: 6.3V; Datasheet: ABA0000CE12.pdf
C27 = CAP_NP: CAP, 0.022uF, 50V, ±20%, X7R, 0603; Manufacturer: TDK Corporation; ManufacturerPN: C1608X7R1H223M; SiLabsPN: C0603X7R500-223M; Tolerance: ±20%; Type: X7R; Voltage: 50V; Datasheet: general_B11.pdf
C28 = CAP_NP: CAP, 2.2nF, 50V, ±20%, X7R, 0603; Installed Component: NI; Manufacturer: Venkel; ManufacturerPN: C0603X7R500-222M; SiLabsPN: C0603X7R500-222M; Tolerance: ±20%; Type: X7R; Voltage: 50V; Datasheet: PID_C.pdf
C29 = CAP_NP: CAP, 0.1uF, 100V, ±10%, X7R, 0805; Manufacturer: Venkel; ManufacturerPN: C0805X7R101-104K; SiLabsPN: C0805X7R101-104K; Tolerance: ±10%; Type: X7R; Voltage: 100V; Datasheet: PID_C.pdf
C30 = CAP_NP: CAP, 0.047uF, 250V, ±10%, X7R, 1206; Manufacturer: Venkel; ManufacturerPN: C1206X7R251-473K; SiLabsPN: C1206X7R251-473K; Tolerance: ±10%; Type: X7R; Voltage: 250V; Datasheet: PID_C.pdf
C31 = CAP_NP: CAP, 220nF, 16V, ±5%, X7R, 0603; Manufacturer: Kemet; ManufacturerPN: C0603C224J4RACTU; SiLabsPN: C0603X7R160-224J; Tolerance: ±5%; Type: X7R; Voltage: 16V; Datasheet: KEM_C1002_X7R_SMD.pdf
C32 = CAP_NP: CAP, 4.7nF, 50V, ±10%, X7R, 0603; Installed Component: NI; Manufacturer: Venkel; ManufacturerPN: C0603X7R500-472K; SiLabsPN: C0603X7R500-472K; Tolerance: ±10%; Type: X7R; Voltage: 50V; Datasheet: PID_C.pdf
C34 C114 = CAP_NP: CAP, 820pF, 200V, ±10%, C0G, 0805; Installed Component: NI; Manufacturer: Venkel; ManufacturerPN: C0805C0G201-821KNE; SiLabsPN: C0805C0G201-821K; Tolerance: ±10%; Type: C0G; Voltage: 200V; Datasheet: PID_C.pdf
C35 C36 = CAP_NP: CAP, 1nF, 2000V, ±5%, X7R, 1206; Installed Component: NI; Manufacturer: Kemet; ManufacturerPN: C1206C102JGRACTU; SiLabsPN: C1206C102JGRACTU; Tolerance: ±5%; Type: X7R; Voltage: 2000V; Datasheet: KEM_C1010_X7R_HV_SMD-1102742.pdf
C37 C47 = CAP_NP: CAP, 1uF, 50V, ±10%, X7R, 0805; Manufacturer: Samsung; ManufacturerPN: CL21B105KBFNNNE; SiLabsPN: C0805X7R500-105K; Tolerance: ±10%; Type: X7R; Voltage: 50V; Datasheet: CL21B105KBFNNNE.pdf
C38 = CAP_NP: CAP, 2.2uF, 10V, ±10%, X7R, 0603; Manufacturer: Venkel; ManufacturerPN: C0603X7R100-225K; SiLabsPN: C0603X7R100-225K; Tolerance: ±10%; Type: X7R; Voltage: 10V; Datasheet: PID_C.pdf
C39 = CAP_NP: CAP, 0.01uF, 25V, ±10%, X8R, 0603; FPLIST: C0603,C0603L; Manufacturer: KEMET; ManufacturerPN: C0603C103K3HACAUTO; Rating: -55°C to +150°C; SiLabsPN: C0603X8R250-103K; Tolerance: ±10%; Type: X8R; Voltage: 25V; Datasheet: KEM_C1007_X8R_ULTRA_150C_SMD.pdf
C41 = CAP_NP: CAP, 1nF, 25V, ±10%, X5R, 0603; Manufacturer: Venkel; ManufacturerPN: C0603X5R250-102K; SiLabsPN: C0603X5R250-102K; Tolerance: ±10%; Type: X5R; Voltage: 25V; Datasheet: PID_C.pdf
C43 = CAP_NP: CAP, 0.01uF, 16V, ±20%, X7R, 0603; Installed Component: NI; Manufacturer: Venkel; ManufacturerPN: C0603X7R160-103M; SiLabsPN: C0603X7R160-103M; Tolerance: ±20%; Type: X7R; Voltage: 16V; Datasheet: PID_C.pdf
C44 = CAP_NP: CAP, 470pF, 25V, ±20%, X7R, 0603; Installed Component: NI; Manufacturer: Venkel; ManufacturerPN: C0603X7R250-471M; SiLabsPN: C0603X7R250-471M; Tolerance: ±20%; Type: X7R; Voltage: 25V; Datasheet: PID_C.pdf
C45 = CAP_NP: CAP, 0.1uF, 10V, ±10%, X7R, 0603; FPLIST: C0603,C0603L; Manufacturer: Venkel; ManufacturerPN: C0603X7R100-104K; SiLabsPN: C0603X7R100-104K; Tolerance: ±10%; Type: X7R; Voltage: 10V; Datasheet: PID_C.pdf
C46 = CAP_NP: CAP, 1nF, 50V, ±5%, C0G, 0603; Manufacturer: Venkel; ManufacturerPN: C0603C0G500-102J; SiLabsPN: C0603COG500-102J; Tolerance: ±5%; Type: C0G; Voltage: 50V; Datasheet: PID_C.pdf
C48 = CAP_NP: CAP, 0.1uF, 50V, ±10%, X7R, 0805; Manufacturer: Venkel; ManufacturerPN: C0805X7R500-104K; SiLabsPN: C0805X7R500-104K; Tolerance: ±10%; Type: X7R; Voltage: 50V; Datasheet: PID_C.pdf
C49 = CAP_NP: CAP, 1nF, 50V, ±5%, C0G, 0603; Installed Component: NI; Manufacturer: Venkel; ManufacturerPN: C0603C0G500-102J; SiLabsPN: C0603COG500-102J; Tolerance: ±5%; Type: C0G; Voltage: 50V; Datasheet: PID_C.pdf
D2 = DIODE_ZENER: DIO, ZENER, 15V, 500mW, SOD123; Installed Component: NI; Manufacturer: On Semi; ManufacturerPN: MMSZ4702T1G; Rating: 500mW; SiLabsPN: MMSZ4702T1G; Tolerance: 5%; Type: Zener; Datasheet: MMSZ4678T1-D.pdf
D5 = DIODE: DIO, FAST, 100V, 1.0A, SMA; Manufacturer: Diodes Inc.; Rating: 1.0A; Type: Fast; Voltage: 100V; Datasheet: ds14001.pdf
D6 = DIODE: DIO, FAST, 150V, 1.0A, SMA; Manufacturer: Diodes Inc.; Rating: 1.0A; Type: Fast; Voltage: 150V; Datasheet: ds14001.pdf
D7 D10 = DIODE_SCHOTTKY_DUAL_ANODE_3PIN: DIO, SCHOTTKY, 40V, 10A, POWERDI-5; Installed Component: NI; Manufacturer: Diodes Inc.; ManufacturerPN: PDS1040-13; Rating: 10A; SiLabsPN: PDS1040-13; Type: Schottky; Voltage: 40V; Datasheet: ds30538-79818.pdf
D8 D11 D12 D14 D15 D17 = DIODE: DIO, SINGLE, 100V, 300mA, SOD123; Manufacturer: Diodes Inc.; ManufacturerPN: 1N4148W-7-F; Rating: 300mA; SiLabsPN: 1N4148W-7-F; Type: Single; Voltage: 100V; Datasheet: ds30086.pdf
D9 = LED: LED, GREEN, 574nm, 5mA, 2.0V, 20mcd, 0603; Manufacturer: LUMEX INC; ManufacturerPN: SML-LXFP0603SUGCTR; Rating: 5mA; SiLabsPN: SML-LXFP0603SUGCTR; Type: SMT; Voltage: 2.0V; Datasheet: SML-LXFP0603SUGCTR-272463.pdf
D13 = DIODE_ZENER: DIO, ZENER, 16V, 500mW, SOD123; Manufacturer: On Semi; ManufacturerPN: MMSZ4703T1G; Rating: 500mW; SiLabsPN: MMSZ4703T1G; Tolerance: 5%; Type: Zener; Datasheet: MMSZ4678T1-D.pdf
D16 = DIODE_ZENER: DIO, ZENER, 15V, 500mW, SOD123; Manufacturer: On Semi; ManufacturerPN: MMSZ4702T1G; Rating: 500mW; SiLabsPN: MMSZ4702T1G; Tolerance: 5%; Type: Zener; Datasheet: MMSZ4678T1-D.pdf
J4 = BINDING-POST: CONN, BANANA JACK, Threaded uninsulated; Manufacturer: ABBATRON HH SMITH; ManufacturerPN: 101; Rating: 15A; SiLabsPN: 101; Silk: +; Type: BANANA; Datasheet: SD-101.pdf
J5 = BINDING-POST: CONN, BANANA JACK, Threaded uninsulated; Manufacturer: ABBATRON HH SMITH; ManufacturerPN: 101; Rating: 15A; SiLabsPN: 101; Type: BANANA; Datasheet: SD-101.pdf
L2 = INDUCTOR: INDUCTOR, POWER, 2.2 uH, ±20%, 2.0A, Unshielded, SMD; Manufacturer: Murata; ManufacturerPN: 84222C; Rating: 2A; SiLabsPN: 84222C; Tolerance: ±20%; Type: Unshielded; Datasheet: kmp_8400.pdf
L3 = INDUCTOR: INDUCTOR, POWER, Shielded, 3.3uH, ±20%, SMD; Manufacturer: Coilcraft; ManufacturerPN: XAL1010-332MEB; Rating: 25A; SiLabsPN: XAL1010-332MEB; Tolerance: ±20%; Type: Shielded; Datasheet: xal1010.pdf
L4 = INDUCTOR: INDUCTOR, POWER, Shielded, 1mH, 0.2A, SMT; Manufacturer: Wurth Elektronik; ManufacturerPN: 74404054102; Rating: 0.2A; SiLabsPN: 74404054102; Tolerance: ±20%; Type: Shielded; Datasheet: 74404054102.pdf
Q3 = NPN_3PIN: TRANSISTOR, NPN, 60V, 2A, 2W, MEDIUM POWER, SOT89; Installed Component: NI; Manufacturer: Diodes Inc.; Rating: 2A; Type: NPN; Voltage: 60V; Datasheet: FCX491-88689.pdf
Q4 = NPN_3PIN: TRANSISTOR, NPN, 60V, 2A, 2W, MEDIUM POWER, SOT89; Manufacturer: Diodes Inc.; Rating: 2A; Type: NPN; Voltage: 60V; Datasheet: FCX491-88689.pdf
Q5 = NPN_3PIN: TRANSISTOR, NPN, 40V, 200mA, GP, SOT23; Manufacturer: Fairchild; Rating: 200mA; Type: NPN; Voltage: 40V; Datasheet: MMBT3904.pdf
Q6 = NFET_PWR_9PIN: TRANSISTOR, MOSFET, N-CHNL, 100V, 23A, POWERPAK-SO-8; Manufacturer: Vishay; ManufacturerPN: SQJ476EP-T1_GE3; Rating: 23A; SiLabsPN: SQJ476EP-T1_GE3; Type: N-CHNL; Voltage: 100V; Datasheet: sqj476ep.pdf
Q7 = PFET_POWER33: TRANSISTOR, MOSFET, P-CHNL, -150V, -3.0A, 1.5Ohms, POWER33; Manufacturer: Fairchild; Rating: -3.0A; Type: P-CHNL; Voltage: -150V; Datasheet: FDMC2523P-D.pdf
R32 = RES: RES, 3.0 Ohm, 1/10W, ±5%, ThickFilm, 0603; Manufacturer: Venkel; ManufacturerPN: CR0603-10W-3R0JT; Rating: 1/10W; SiLabsPN: CR0603-10W-3R0J; Tolerance: ±5%; Type: ThickFilm; Datasheet: PID_CR.pdf
R33 = RES: RES, 95.3K, 1/16W, ±1%, ThickFilm, 0603; Manufacturer: Venkel; ManufacturerPN: CR0603-16W-9532F; Rating: 1/16W; SiLabsPN: CR0603-16W-9532F; Silk: 50kHz; Tolerance: ±1%; Type: ThickFilm; Datasheet: PID_CR.pdf
R35 R38 = RES: RES, 6.8 Ohm, 1/8W, ±5%, ThickFilm, 1206; Installed Component: NI; Manufacturer: Venkel; ManufacturerPN: CR1206-8W-6R8J; Rating: 1/8W; SiLabsPN: CR1206-8W-6R8J; Tolerance: ±5%; Type: ThickFilm; Datasheet: PID_CR.pdf
R36 R40 = RES: RES, 10.0 Ohm, 1/16W, ±1%, ThickFilm, 0603; Manufacturer: Venkel; ManufacturerPN: CR0603-16W-10R0F; Rating: 1/16W; SiLabsPN: CR0603-16W-10R0F; Tolerance: ±1%; Type: ThickFilm; Datasheet: PID_CR.pdf
R37 = RES: RES, 2.2K, 1/4W, ±5%, ThickFilm, 1206; Manufacturer: Venkel; ManufacturerPN: CR1206-4W-222JT; Rating: 1/4W; SiLabsPN: CR1206-4W-222J; Tolerance: ±5%; Type: ThickFilm; Datasheet: PID_CR.pdf
R39 R132 = RES: RES, 10 Ohm, 1/4W, ±1%, ThickFilm, 1206; Installed Component: NI; Manufacturer: Venkel; ManufacturerPN: CR1206-4W-10R0F; Rating: 1/4W; SiLabsPN: CR1206-4W-10R0F; Tolerance: ±1%; Type: ThickFilm; Datasheet: PID_CR.pdf
R41 = RES: RES, 3.24K, 1/10W, ±1%, ThickFilm, 0603; Manufacturer: Venkel; ManufacturerPN: CR0603-10W-3241F; Rating: 1/10W; SiLabsPN: CR0603-10W-3241F; Tolerance: ±1%; Type: ThickFilm; Datasheet: PID_CR.pdf
R42 = RES: RES, 2.15K, 1/10W, ±1%, ThickFilm, 0603; Manufacturer: Venkel; ManufacturerPN: CR0603-10W-2151F; Rating: 1/10W; SiLabsPN: CR0603-10W-2151F; Tolerance: ±1%; Type: ThickFilm; Datasheet: PID_CR.pdf
R43 = RES: RES, 24K, 1/10W, ±1%, ThickFilm, 0603; Manufacturer: Panasonic; ManufacturerPN: ERJ-3EKF2402V; Rating: 1/10W; SiLabsPN: CR0603-10W-2402F; Tolerance: ±1%; Type: ThickFilm; Datasheet: AOA0000CE2.pdf
R44 = RES: RES, 36.5K, 1/16W, ±1%, ThickFilm, 0603; Manufacturer: Venkel; ManufacturerPN: CR0603-16W-3652F; Rating: 1/16W; SiLabsPN: CR0603-16W-3652F; Tolerance: ±1%; Type: ThickFilm; Datasheet: PID_CR.pdf
R45 = RES: RES, 3.3K, 1/10W, ±1%, ThickFilm, 0805; Manufacturer: Venkel; ManufacturerPN: CR0805-10W-3301F; Rating: 1/10W; SiLabsPN: CR0805-10W-3301F; Tolerance: ±1%; Type: ThickFilm; Datasheet: PID_CR.pdf
R46 = RES: RES, 1K, 1/10W, ±1%, ThickFilm, 0603; Installed Component: NI; Manufacturer: Venkel; ManufacturerPN: CR0603-10W-1001F; Rating: 1/10W; SiLabsPN: CR0603-10W-1001F; Tolerance: ±1%; Type: ThickFilm; Datasheet: PID_CR.pdf
R47 = RES: RES, 0 Ohm, 1A, ThickFilm, 0603; FPLIST: R0603,R0603L; Installed Component: NI; Manufacturer: Venkel; ManufacturerPN: CR0603-16W-000; Rating: 1A; SiLabsPN: CR0603-16W-000; Type: ThickFilm; Datasheet: PID_CR.pdf
R49 R50 = RES: RES, 0 Ohm, 1A, ThickFilm, 0603; FPLIST: R0603,R0603L; Manufacturer: Venkel; ManufacturerPN: CR0603-16W-000; Rating: 1A; SiLabsPN: CR0603-16W-000; Type: ThickFilm; Datasheet: PID_CR.pdf
R51 = RES: RES, 12.1K, 1/16W, ±1%, ThickFilm, 0603; Manufacturer: Venkel; ManufacturerPN: CR0603-16W-1212F; Rating: 1/16W; SiLabsPN: CR0603-16W-1212F; Tolerance: ±1%; Type: ThickFilm; Datasheet: PID_CR.pdf
R52 = RES: RES, 0.039 Ohm, 1W, ±1%, ThickFilm, 1206; Manufacturer: Panasonic; ManufacturerPN: ERJ-8CWFR039V; Rating: 1W; SiLabsPN: ERJ-8CWFR039V; Tolerance: ±1%; Type: ThickFilm; Datasheet: AOA0000C313.pdf
R53 = RES: RES, 510 Ohm, 1/10W, ±1%, ThickFilm, 0603; Installed Component: NI; Manufacturer: Venkel; ManufacturerPN: CR0603-10W-5100F; Rating: 1/10W; SiLabsPN: CR0603-10W-5100F; Tolerance: ±1%; Type: ThickFilm; Datasheet: PID_CR.pdf
R54 = RES: RES, 510 Ohm, 1/10W, ±1%, ThickFilm, 0603; Manufacturer: Venkel; ManufacturerPN: CR0603-10W-5100F; Rating: 1/10W; SiLabsPN: CR0603-10W-5100F; Tolerance: ±1%; Type: ThickFilm; Datasheet: PID_CR.pdf
R55 = RES: RES, 0.1 Ohm, 1/2W, ±1%, ThickFilm, 1206; Manufacturer: Venkel; ManufacturerPN: LCR1206-R100F; Rating: 1/2W; SiLabsPN: LCR1206-R100F; Tolerance: ±1%; Type: ThickFilm; Datasheet: PID_CR.pdf
R56 = RES: RES, 10K, 1/8W, ±1%, ThickFilm, 0805; Manufacturer: Venkel; ManufacturerPN: CR0805-8W-1002F; Rating: 1/8W; SiLabsPN: CR0805-8W-1002F; Tolerance: ±1%; Type: ThickFilm; Datasheet: PID_CR.pdf
R57 = RES: RES, 3 Ohm, 1/8W, ±1%, ThickFilm, 0805; Manufacturer: Venkel; ManufacturerPN: CR0805-8W-3R00FT; Rating: 1/8W; SiLabsPN: CR0805-8W-3R00F; Tolerance: ±1%; Type: ThickFilm; Datasheet: PID_CR.pdf
T2 = LINKCOM_EPD-13: TRANSFORMER, Forward, 100uH, 70W, SMD, 165°C; Manufacturer: LinkCom; Rating: 70W; Type: FORWARD; Voltage: 5V; Datasheet: LDT1056-51.pdf
TP18 = TEST_POINT: TESTPOINT, BLACK, PTH; Manufacturer: Kobiconn; ManufacturerPN: 151-203-RC; SiLabsPN: 151-203; Silk: vpos; Type: Loop; Datasheet: KC-300780.pdf
TP19 TP33 = TEST_POINT: TESTPOINT, BLACK, PTH; Manufacturer: Kobiconn; ManufacturerPN: 151-203-RC; SiLabsPN: 151-203; Silk: vss; Type: Loop; Datasheet: KC-300780.pdf
TP20 = TEST_POINT: TESTPOINT, BLACK, PTH; Manufacturer: Kobiconn; ManufacturerPN: 151-203-RC; SiLabsPN: 151-203; Silk: sec+; Type: Loop; Datasheet: KC-300780.pdf
TP21 TP23 = TEST_POINT: TESTPOINT, BLACK, PTH; Manufacturer: Kobiconn; ManufacturerPN: 151-203-RC; SiLabsPN: 151-203; Silk: vout; Type: Loop; Datasheet: KC-300780.pdf
TP22 = TEST_POINT: TESTPOINT, BLACK, PTH; Manufacturer: Kobiconn; ManufacturerPN: 151-203-RC; SiLabsPN: 151-203; Silk: vt15; Type: Loop; Datasheet: KC-300780.pdf
TP24 = TEST_POINT: TESTPOINT, BLACK, PTH; Manufacturer: Kobiconn; ManufacturerPN: 151-203-RC; SiLabsPN: 151-203; Silk: sw; Type: Loop; Datasheet: KC-300780.pdf
TP25 = TEST_POINT: TESTPOINT, BLACK, PTH; Manufacturer: Kobiconn; ManufacturerPN: 151-203-RC; SiLabsPN: 151-203; Silk: syncl; Type: Loop; Datasheet: KC-300780.pdf
TP26 = TEST_POINT: TESTPOINT, BLACK, PTH; Manufacturer: Kobiconn; ManufacturerPN: 151-203-RC; SiLabsPN: 151-203; Silk: v11; Type: Loop; Datasheet: KC-300780.pdf
TP27 = TEST_POINT: TESTPOINT, BLACK, PTH; Manufacturer: Kobiconn; ManufacturerPN: 151-203-RC; SiLabsPN: 151-203; Silk: swgate; Type: Loop; Datasheet: KC-300780.pdf
TP28 = TEST_POINT: TESTPOINT, BLACK, PTH; Manufacturer: Kobiconn; ManufacturerPN: 151-203-RC; SiLabsPN: 151-203; Silk: loop; Type: Loop; Datasheet: KC-300780.pdf
TP29 = TEST_POINT: TESTPOINT, BLACK, PTH; Manufacturer: Kobiconn; ManufacturerPN: 151-203-RC; SiLabsPN: 151-203; Silk: gndi; Type: Loop; Datasheet: KC-300780.pdf
TP30 = TEST_POINT: TESTPOINT, BLACK, PTH; Manufacturer: Kobiconn; ManufacturerPN: 151-203-RC; SiLabsPN: 151-203; Silk: extgd; Type: Loop; Datasheet: KC-300780.pdf
TP31 = TEST_POINT: TESTPOINT, BLACK, PTH; Manufacturer: Kobiconn; ManufacturerPN: 151-203-RC; SiLabsPN: 151-203; Silk: sec-; Type: Loop; Datasheet: KC-300780.pdf
TP32 = TEST_POINT: TESTPOINT, BLACK, PTH; Manufacturer: Kobiconn; ManufacturerPN: 151-203-RC; SiLabsPN: 151-203; Silk: swisns; Type: Loop; Datasheet: KC-300780.pdf
TP34 = TEST_POINT: TESTPOINT, BLACK, PTH; Manufacturer: Kobiconn; ManufacturerPN: 151-203-RC; SiLabsPN: 151-203; Silk: erout; Type: Loop; Datasheet: KC-300780.pdf
TP35 = TEST_POINT: TESTPOINT, BLACK, PTH; Manufacturer: Kobiconn; ManufacturerPN: 151-203-RC; SiLabsPN: 151-203; Silk: GC; Type: Loop; Datasheet: KC-300780.pdf
TP36 = TEST_POINT: TESTPOINT, BLACK, PTH; Manufacturer: Kobiconn; ManufacturerPN: 151-203-RC; SiLabsPN: 151-203; Silk: isns; Type: Loop; Datasheet: KC-300780.pdf
TP37 = TEST_POINT: TESTPOINT, BLACK, PTH; Manufacturer: Kobiconn; ManufacturerPN: 151-203-RC; SiLabsPN: 151-203; Silk: GF; Type: Loop; Datasheet: KC-300780.pdf
TP38 = TEST_POINT: TESTPOINT, BLACK, PTH; Manufacturer: Kobiconn; ManufacturerPN: 151-203-RC; SiLabsPN: 151-203; Silk: cgate; Type: Loop; Datasheet: KC-300780.pdf
U5 = NFET_PWR_9PIN: TRANSISTOR, MOSFET, N-CHNL, 150V, 29A, POWERPAK-SO-8; Manufacturer: Vishay; ManufacturerPN: SIR632DP-T1-RE3; Rating: 29A; SiLabsPN: SIR632DP-T1-RE3; Type: N-CHNL; Voltage: 150V; Datasheet: sir632dp.pdf
U6 = Si34071: IC, IEEE 802.3bt-Compliant POE+ PD Interface, QFN32; Manufacturer: Skyworks; ManufacturerPN: Si34071-A01-GM; SiLabsPN: Si34071-A01-GM; Type: PD; Voltage: 120V; Datasheet: si3407x-datasheet.pdf
U9 U10 = NFET_PWR_9PIN: TRANSISTOR, MOSFET, N-CHNL, 40V, 100A, POWERPAK-SO-8; Manufacturer: Infineon Technologies; Rating: 100A; Type: N-CHNL; Voltage: 40V; Datasheet: Infineon-IPC100N04S5-1R9-DS-v01_02-EN.pdf
U11 = FAN3100CSX: IC, GATE DRIVER, 3A, CMOS INPUT, SOT23-5; Manufacturer: ON Semiconductor; Rating: 4A; Type: Gate Driver; Datasheet: FAN3100T-D.pdf

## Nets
gndi: C22.2 C23.2 C24.2 C25.2 C26.2 C27.2 C28.1 C29.2 C40.2 C42.2 C112.2 C113.2 D2.A(ANODE) D7.A1(ANODE) D7.A2(ANODE) D9.K(CATHODE) D10.A1(ANODE) D10.A2(ANODE) D16.A(ANODE) J5.1(BP) J103.1 R37.1 R39.2 R51.1 R129.1 TP29.1(Point) U8.A(Anode) U9.1(S1) U9.2(S2) U9.3(S3) U10.1(S1) U10.2(S2) U10.3(S3) U102.E(EMITTER) U103.1(GND)
v11: C31.1 C47.2 TP26.1(Point) U6.24(v11) U11.1(VDD) U11.3(IN+)
vdd: C45.2 R41.2 U6.4(vdd) U6.8(nsleep)
vss: C14.2 C15.2 C16.2 C17.2 C18.2 C19.2 C20.2 C21.2 C31.2 C37.2 C38.2 C39.2 C40.1 C42.1 C43.2 C44.2 C45.1 C47.1 D6.A(ANODE) D12.A(ANODE) D13.A(ANODE) D17.K(CATHODE) Q7.2(SOURCE) Q7.3(SOURCE) Q7.S(SOURCE) R52.1 R55.2 R56.1 R132.1 T2.5 TP19.1(Point) TP33.1(Point) U6.3(fbl) U6.31(vss) U7.E(EMITTER) U11.2(GND)
BS: C1.2 C6.2
cgate: C48.2 D17.A(ANODE) Q7.G(GATE) R56.2 TP38.1(Point)
clsdet: Q108.C(COLLECTOR) TP10.1(Point) U6.14(clsdet)
clsmode: R116.1 R121.2 TP14.1(Point) U6.30(clsmode)
clsvdd: C108.1 D104.A(ANODE) Q107.E(EMMITER) R114.2 R115.2 R116.2 R118.2 R119.2 R120.2 R127.2 R130.2 TP7.1(Point) U6.12(clsvdd)
erout: R41.1 R47.2 TP34.1(Point) U6.2(erout) U7.C(COLLECTOR)
extgd: D11.K(CATHODE) R40.1 TP30.1(Point) U6.25(extgd)
exthsw: Q6.4(G) U6.6(exthsw)
hso: Q6.5(D5) Q6.6(D6) Q6.7(D7) Q6.8(D8) Q6.9(D9) R55.1 TP36.1(Point) U6.1(isns) U6.13(hso)
LABEL: LB1.1(LABEL)
mctrl: C111.1 R119.1 TP9.1(Point) U6.15(mctrl)
MX1+: C2.2 Q1.1(G1) Q1.4(G2) Q1.15(INPUT22) Q1.16(INPUT21) T1.24(MCT1) TP3.1(Point)
MX2+: C3.2 Q1.9(G3) Q1.12(G4) Q1.13(INPUT11) Q1.14(INPUT12) T1.21(MCT2) TP2.1(Point)
MX3+: C4.2 Q2.1(G1) Q2.4(G2) Q2.15(INPUT22) Q2.16(INPUT21) T1.18(MCT3) TP5.1(Point)
MX4+: C5.2 Q2.9(G3) Q2.12(G4) Q2.13(INPUT11) Q2.14(INPUT12) T1.15(MCT4) TP4.1(Point)
pri+: C17.1 C18.1 C19.1 C20.1 C21.1 C35.1 C36.1 L2.2 T2.1
rcl: R122.2 U6.16(rcl)
rclass1: R115.1 TP12.1(Point) U6.10(rclass1)
rclass2: R114.1 TP13.1(Point) U6.11(rclass2)
rdet: R48.2 U6.9(rdet)
rfreq: R33.1 U6.17(rfreq)
rx: R130.1 TP16.1(Point) U6.27(rx) U104.C(COLLECTOR)
rxh: J103.3 R125.1 U102.C(COLLECTOR)
sec+: C35.2 C46.2 D5.A(ANODE) D7.K(CATHODE) D14.K(CATHODE) L3.1 Q4.C(COLLECTOR) R35.2 R54.1 T2.9 T2.10 TP20.1(Point) U9.5(D5) U9.6(D6) U9.7(D7) U9.8(D8) U9.9(D9)
sec-: C32.1 C49.2 D10.K(CATHODE) D15.K(CATHODE) Q3.C(COLLECTOR) R53.1 R57.2 T2.6 T2.7 TP31.1(Point) U10.5(D5) U10.6(D6) U10.7(D7) U10.8(D8) U10.9(D9)
sw: C30.2 R38.2 T2.3 TP24.1(Point) U5.5(D5) U5.6(D6) U5.7(D7) U5.8(D8) U5.9(D9)
syncl: TP25.1(Point) U6.23(syncl) U11.4(IN-)
tx: R128.1 TP15.1(Point) U6.21(tx) U102.K(CATHODE)
txh: J103.2 U104.K(CATHODE)
vadc: J103.4 R126.1 R129.2
vcls: D103.A(ANODE) R123.2 TP8.1(Point) U6.29(vcls)
vlogic: C113.1 J103.5 R125.2 R131.1 U103.2(OUT)
vneg: C33.2 C108.2 C110.2 C111.2 FB2.2 Q6.1(S1) Q6.2(S2) Q6.3(S3) Q108.E(EMMITER) R121.1 R123.1 R124.1 TP11.1(Point) TP17.1(Point) U6.18(nc) U6.20(nc) U6.33(pad) U101.A(Anode) U104.E(EMITTER)
vneg_pre: D1.A(ANODE) L1.2 Q1.2(OUTN1) Q1.3(OUTN2) Q1.10(OUTN3) Q1.11(OUTN4) Q2.2(OUTN1) Q2.3(OUTN2) Q2.10(OUTN3) Q2.11(OUTN4) TP6.1(Point)
vout: C22.1 C23.1 C24.1 C25.1 C26.1 C27.1 C36.2 C112.1 J4.1(BP) L3.2 R34.2 R36.2 R126.2 TP21.1(Point) TP23.1(Point) U103.3(IN)
vpos: C14.1 C15.1 C16.1 C107.1 FB1.2 L2.1 Q103.E(EMMITER) R32.2 R33.2 R48.1 R109.2 R110.2 R111.2 TP18.1(Point) U6.19(vpos)
vpos_pre: D1.K(CATHODE) L1.3 Q1.5(OUTP1) Q1.6(OUTP2) Q1.7(OUTP3) Q1.8(OUTP4) Q2.5(OUTP1) Q2.6(OUTP2) Q2.7(OUTP3) Q2.8(OUTP4) TP1.1(Point)
vref: R44.1 R49.1 R51.2 U8.REF(VREF)
vt15: C37.1 Q5.E(EMMITER) TP22.1(Point) U6.22(vt15)
N1572190: R36.1 R42.2 R44.2 TP28.1(Point)
N1572222: R42.1 R46.1 U7.A(ANODE)
N1572276: C44.1 R50.2 U6.32(swisns)
N1572494: C43.1 R47.1
N1572496: C41.1 R46.2 U7.K(CATHODE) U8.K(Cathode)
N1578169: J2.6(MX1-) T1.6(TD2-)
N1578177: J2.5(MX2-) T1.9(TD3-)
N1578189: J2.8(MX3-) T1.12(TD4-)
N1578197: J2.7(MX3+) T1.11(TD4+)
N1578209: J2.3(MX1+) T1.5(TD2+)
N1578233: J2.2(MX0-) T1.3(TD1-)
N1578492: J2.1(MX0+) T1.2(TD1+)
N1578985: J1.6(MX1-) T1.19(MX2-)
N1579021: J1.5(MX2-) T1.16(MX3-)
N1579033: J1.8(MX3-) T1.13(MX4-)
N1579041: J1.7(MX3+) T1.14(MX4+)
N1579053: J1.3(MX1+) T1.20(MX2+)
N1579069: J1.2(MX0-) T1.22(MX1-)
N1579081: J1.1(MX0+) T1.23(MX1+)
N1579428: C1.1 R1.2 R2.2 R3.2 R4.2
N1579529: C2.1 R5.2
N1579577: C3.1 R6.2
N1579641: C4.1 R7.2
N1579705: C5.1 R8.2
N1579733: C6.1 R5.1 R6.1 R7.1 R8.1
N1583012: FB1.1 L1.4
N1583016: FB2.1 L1.1
N1585890: J1.4(MX2+) T1.17(MX3+)
N1586017: R1.1 T1.1(TCT1)
N1586046: R2.1 T1.4(TCT2)
N1586058: R3.1 T1.7(TCT3)
N1586070: R4.1 T1.10(TCT4)
N1586305: J2.4(MX2+) T1.8(TD3+)
N1656557: C33.1 R32.1
N1661859: C107.2 D102.A(ANODE) Q104.B(BASE) Q104.C(COLLECTOR) Q105.B(BASE) R110.1 R113.2
N1661867: Q106.E(EMMITER) Q107.B(BASE) R117.2 R118.1
N1661875: D103.K(CATHODE) R113.1
N1661883: C109.2 C110.1 Q106.B(BASE) R112.1 R117.1 U101.K(Cathode)
N1661895: C109.1 R120.1 R124.2 U101.REF(VREF)
N1662077: D102.K(CATHODE) Q106.C(COLLECTOR) Q107.C(COLLECTOR) R111.1
N1662085: Q105.E(EMMITER) R109.1
N1662329: Q103.B(BASE) Q103.C(COLLECTOR) Q104.E(EMMITER)
N1662443: Q108.B(BASE) R122.1
N1662667: Q105.C(COLLECTOR) R112.2
N1669474: C41.2 R49.2
N1739033: D9.A(ANODE) R34.1
N1892715: C34.2 R43.1 R50.1 R52.2 TP32.1(Point) U5.1(S1) U5.2(S2) U5.3(S3)
N1892825: D11.A(ANODE) R40.2 R43.2 TP27.1(Point) U5.4(G)
N1959752: D14.A(ANODE) Q4.E(EMMITER) TP37.1(Point) U10.4(G)
N1959776: C46.1 D16.K(CATHODE) Q4.B(BASE) R54.2
N1960678: D15.A(ANODE) Q3.E(EMMITER) R57.1 TP35.1(Point) U9.4(G)
N1994064: R131.2 U104.A(ANODE)
N2008317: R127.1 U102.A(ANODE)
N2054672: C34.1 R38.1
N2062983: C38.1 C39.1 L4.1 Q5.C(COLLECTOR) R45.2
N2106562: C29.1 D5.K(CATHODE) R37.2
N2110977: D13.K(CATHODE) Q5.B(BASE) R45.1
N2130480: C48.1 U11.5(OUT)
N2221184: C30.1 Q7.D(DRAIN)
N2222894: C28.2 R35.1
N2244675: D104.K(CATHODE) R128.2
N2252953: D8.A(ANODE) T2.4
N2253839: D8.K(CATHODE) D12.K(CATHODE) L4.2
N2266379: C49.1 D2.K(CATHODE) Q3.B(BASE) R53.2
N2323701: C114.2 D6.K(CATHODE) T2.2
N2368552: C32.2 R39.1
N2368553: C114.1 R132.2

Not connected (* = marked no-connect by the designer): D102 C(COMMON)*; J103 6*; U6 5(led)* 7(wake)* 26(mode)* 28(nc)*

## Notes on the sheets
sheet 1
- DATA + PoE
- DATA
sheet 2
- Classification BOM
- communication with MCU
- LDO and communication header for host MCU
- communication with MCU
sheet 3
- Input filter
- Use adequate thermal
  plane under the IC,
  connected to VNEG
- Compensation network
- IC supply - VT15
- Parallel with Catch Diode - SR
- Parallel with Forward Diode - SR
- Clamp Driver
